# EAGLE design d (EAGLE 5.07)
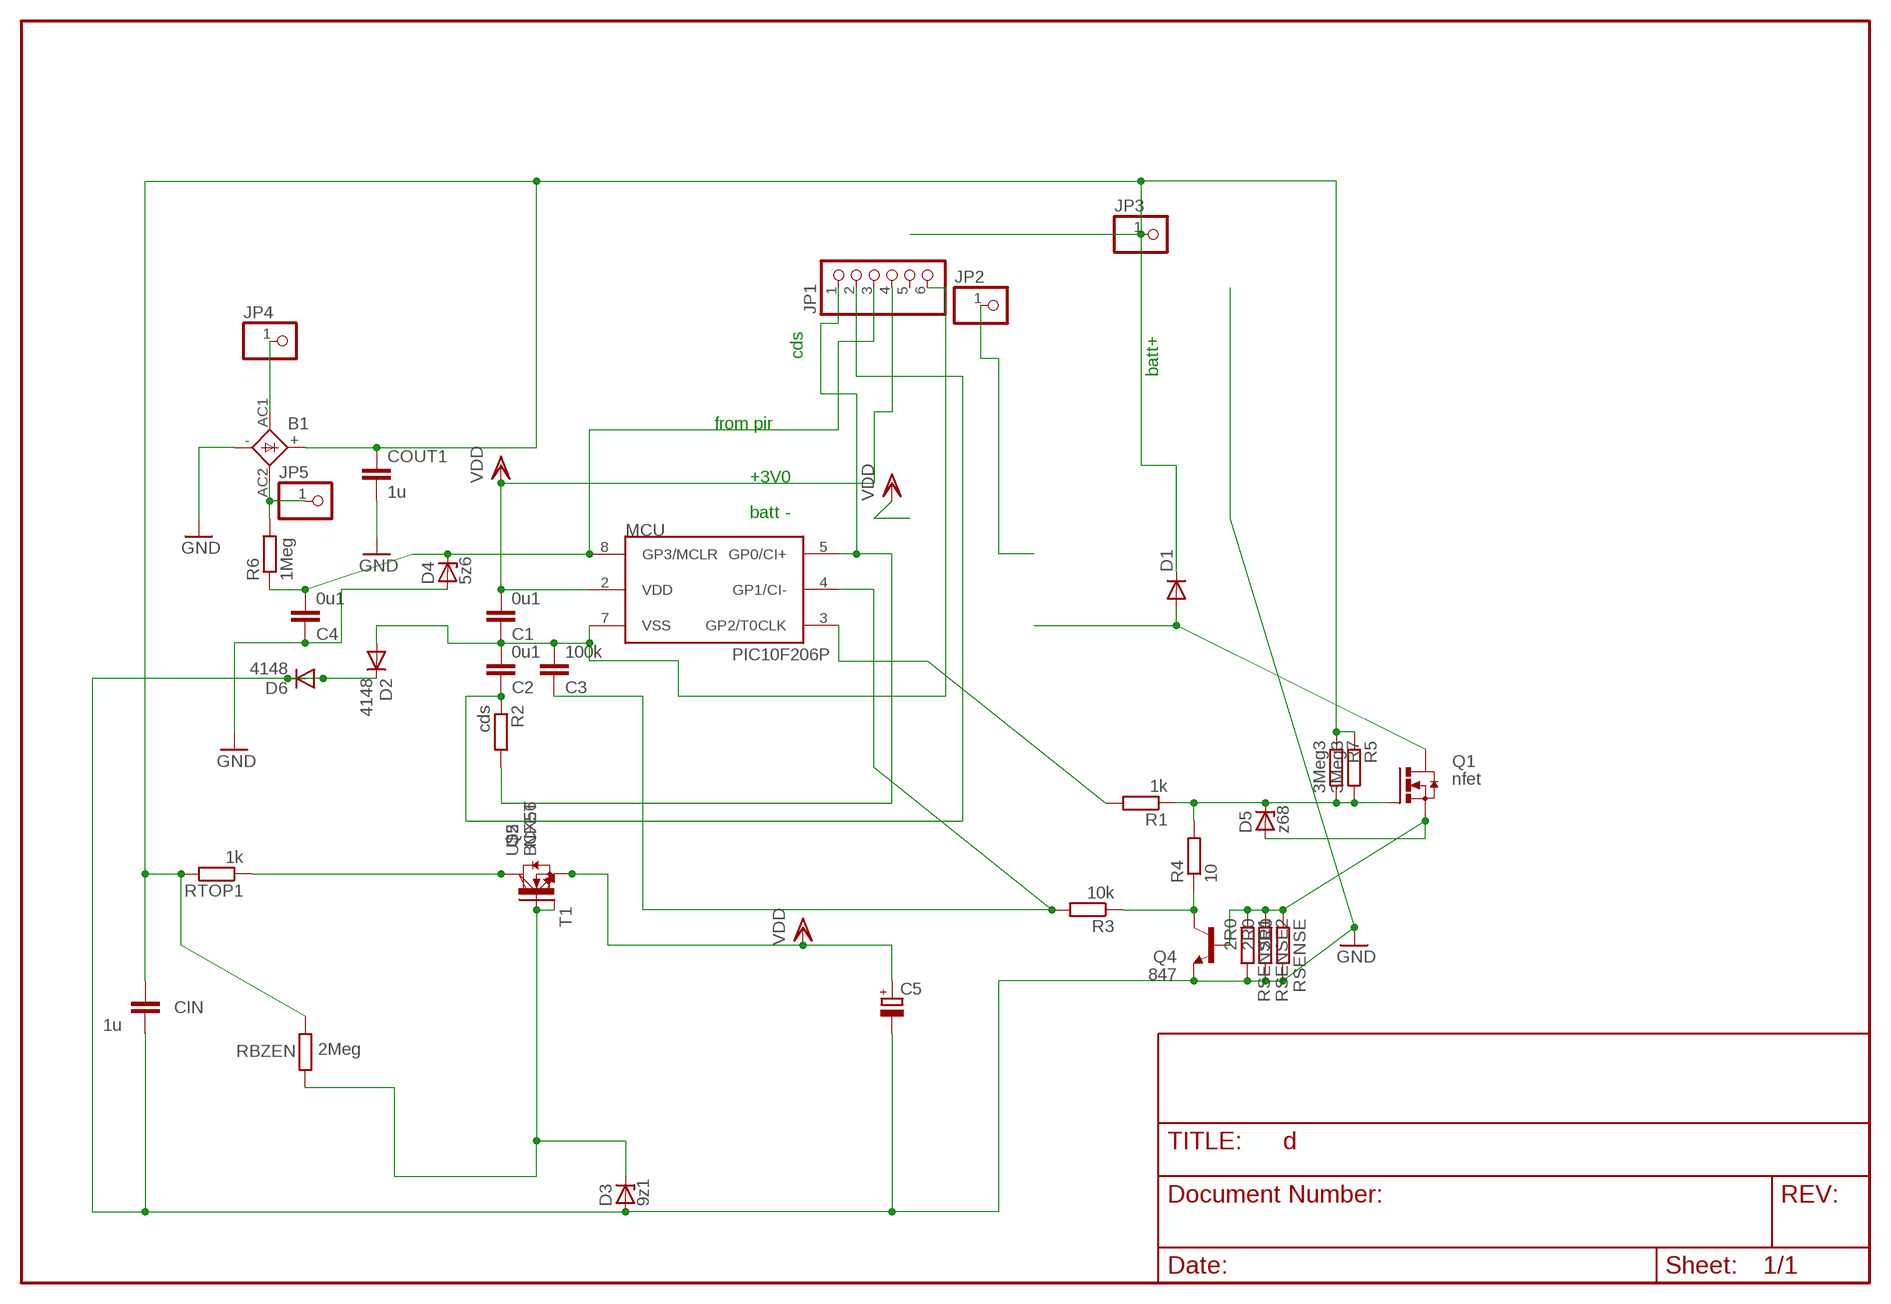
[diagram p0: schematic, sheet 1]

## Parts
B1  1KAB  [1KAB]
C1  0u1  C-EUC1206  [C1206]
C2  0u1  C-EUC0805  [C0805]
C3  100k  C-EUC1206  [C1206]
C4  0u1  C-EUC1206  [C1206]
C5  CPOL-EUSANYO_SMD_C6  [SANYO-OSCON_SMD_C6]
CIN  1u  C-EU050-024X044  [C050-024X044]
COUT1  1u  C-EU075-032X103  [C075-032X103]
D1  DIODE-SMC  [SMC]
D2  4148  1N4148MINIMELF  [MINIMELF]
D3  9z1  ZENER-DIODESOD80C  [SOD80C]
D4  5z6  ZENER-DIODESOD80C  [SOD80C]
D5  z68  ZENER-DIODESOD80C  [SOD80C]
D6  4148  1N4148MINIMELF  [MINIMELF]
JP1  PINHD-1X6  [1X06BOX]
JP2  PINHD-1X11X0.4  [1X01]
JP3  PINHD-1X11X0.4  [1X01]
JP4  PINHD-1X11X0.4  [1X01]
JP5  PINHD-1X11X0.4  [1X01]
MCU  PIC10F206P  [DIL8]
Q1  nfet  N-HEXFET_DPAK-  [TO252]
Q4  847  BC847ASMD  [SOT23]
Q5  NFET  N-HEXFET_DPAK-  [TO252]
R1  1k  R-EU_R0805  [R0805]
R2  cds  R-EU_0204/2V  [0204V]
R3  10k  R-EU_R1206  [R1206]
R4  10  R-EU_R1206  [R1206]
R5  3Meg3  R-EU_R2010  [R2010]
R6  1Meg  R-EU_  [0207/27]
R7  3Meg3  R-EU_0207/15  [0207/15]
RBZEN  2Meg  R-EU_0204/7  [0204/7]
RSENSE  2R0  R-EU_0207/15  [0207/15]
RSENSE1  2R0  R-EU_R1210  [R1210]
RSENSE2  2R0  R-EU_R2512  [R2512]
RTOP1  1k  R-EU_R1206  [R1206]
T1  -NPN-TO126V  [TO126V]
U$2  BCX56  [SOT223]

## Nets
AC1: B1.AC1 JP4.1
AC2: B1.AC2 JP5.1 R6.2
C: Q5.3(D) RTOP1.1 T1.2(C) U$2.2(C)
CB: D3.C Q5.1(G) RBZEN.2 T1.3(B) U$2.1(B)
GND: B1.- C4.1 C5.- CIN.2 COUT1.2 D2.C D3.A D4.A D6.A D6.C Q4.2(E) RSENSE1.2 RSENSE2.2 RSENSE.2
HOT: D1.A Q1.3(D)
LED-: JP2.1
N$1: Q4.3(C) R3.1 R4.1
N$2: JP1.1 MCU.5(GP0/CI+) R2.2
N$4: C3.1 MCU.4(GP1/CI-) R3.2
N$6: C4.2 D4.C JP1.3 MCU.8(GP3/MCLR) R6.1
N$7: D5.C Q1.1(G) R1.1 R4.2 R5.2 R7.2
N$11: C2.1 JP1.2 R2.1
N$14: MCU.3(GP2/T0CLK) R1.2
N$17: D5.A Q1.2(S) Q4.1(B) RSENSE1.1 RSENSE2.1 RSENSE.1
VDD: C1.2 C5.+ JP1.4 MCU.2(VDD) Q5.2(S) T1.1(E) U$2.3(E)
VPLUS: B1.+ CIN.1 COUT1.1 D1.C JP3.1 R5.1 R7.1 RBZEN.1 RTOP1.2
VSS: C1.1 C2.2 C3.2 D2.A JP1.6 MCU.7(VSS)
Unconnected: JP1.5

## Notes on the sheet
- cds
- batt+
- from pir
- +3V0
- batt -

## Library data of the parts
B1 = rectifier:1KAB: RECTIFIER grid 5,08 x 5,08 mm
C1-C4 CIN COUT1 = rcl:C-EU: CAPACITOR, European symbol
C5 = rcl-2:CPOL-EU: POLARIZED CAPACITOR, European symbol
D1 = diode-1:DIODE-: DIODE
D2 D6 = diode-1:1N4148: DIODE
D3-D5 = diode:ZENER-DIODE: Z-Diode
JP1 = pinhead:PINHD-1X6: PIN HEADER
JP2-JP5 = pinhead:PINHD-1X1: PIN HEADER
MCU = microchip-3:PIC10F2*: uPC nW 0,25/0,5k Program Flash memory Comparator
Q1 Q5 = transistor-power:N-HEXFET_?-*: HEXFET® Power MOSFET
Q4 = transistor-npn:BC847*: NPN Transistor
R1-R5 R7 RBZEN RSENSE RSENSE1 RSENSE2 RTOP1 = rcl:R-EU_: RESISTOR, European symbol
R6 = rcl-2:R-EU_: RESISTOR, European symbol
T1 = transistor:*-NPN-: NPN Transistror BF959 corrected 2008.03.06
U$2 = transistor-power:BCX56

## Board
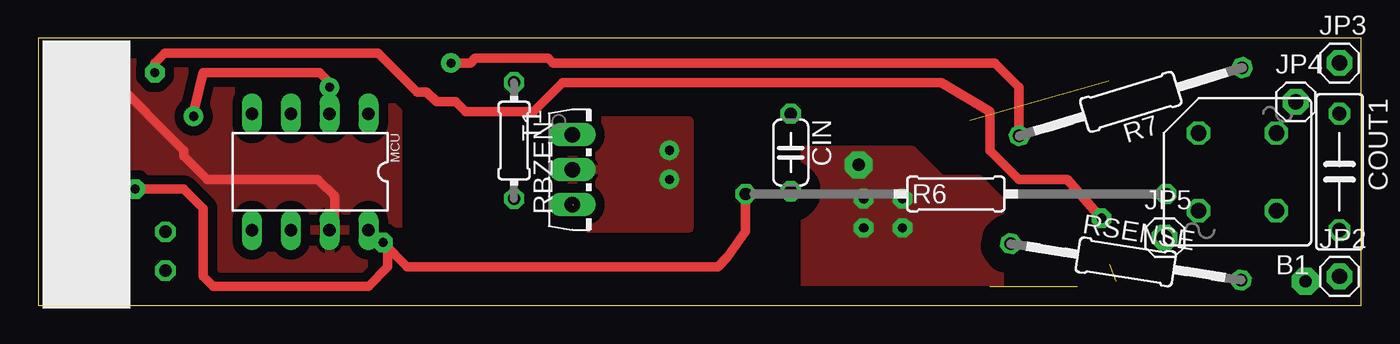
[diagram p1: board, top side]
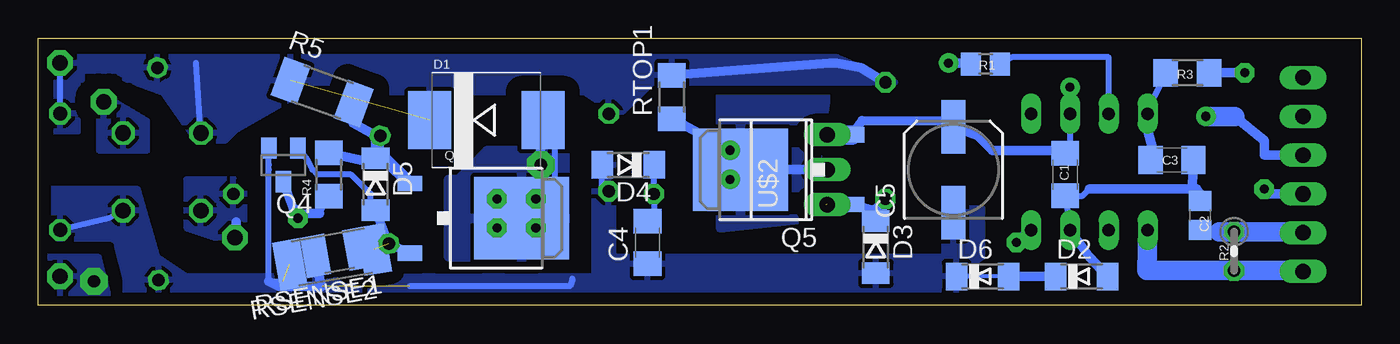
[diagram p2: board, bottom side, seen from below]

Size 86.52 x 17.5 mm. Coordinates in mm from the lower left corner, seen from the top.
Outline: 0,0 86.52,0 86.52,17.5 0,17.5 0,0
Copper layers (1*16): Top 0.035mm / dielectric 1.5mm / Bottom 0.035mm
Design rules "default *": minimum track width 10mil, minimum drill 24mil, track to track 8mil, track to pad 8mil, pad to pad 8mil, via to via 8mil, smd to smd 8mil, copper to edge 20mil, drill to drill 8mil, minimum pad ring 10mil, minimum via ring 8mil, stop-mask expansion 4mil, vias tented up to drill 0mil, thermal gap 10mil

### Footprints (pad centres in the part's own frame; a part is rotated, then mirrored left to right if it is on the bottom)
1KAB = drill 1.016 octagon: + 2.54,-2.54; - -2.54,2.54; AC1 -2.54,-2.54; AC2 2.54,2.54
C1206 = smd 1.6 x 1.8: 1 -1.4,0; 2 1.4,0
C0805 = smd 1.3 x 1.5: 1 -0.95,0; 2 0.95,0
SANYO-OSCON_SMD_C6 = smd 3.5 x 1.6: + 2.8,0; - -2.8,0
C050-024X044 = drill 0.813 octagon: 1 -2.54,0; 2 2.54,0
C075-032X103 = drill 0.914 octagon: 1 -3.81,0; 2 3.81,0
SMC = smd 2.8 x 3.8: A 3.7,0; C -3.7,0
MINIMELF = smd 1.4 x 1.8: A 1.7,0; C -1.7,0
SOD80C = smd 1.4 x 1.8: A 1.7,0; C -1.7,0
1X06BOX = drill 1.016 long: 1 -6.35,0; 2 -3.81,0; 3 -1.27,0; 4 1.27,0; 5 3.81,0; 6 6.35,0
1X01 = drill 1 pad 1.676 octagon: 1 0,0
DIL8 = drill 0.813 long: 1 -3.81,-3.81; 2 -1.27,-3.81; 3 1.27,-3.81; 4 3.81,-3.81; 5 3.81,3.81; 6 1.27,3.81; 7 -1.27,3.81; 8 -3.81,3.81
TO252 = smd 1 x 1.6: 1 -2.28,-3.53; 2 2.28,-3.53 | smd 5.4 x 6.2: 3 0,3.77
SOT23 = smd 1 x 1.4: 1 -0.95,-1.1; 2 0.95,-1.1; 3 0,1.1
R0805 = smd 1.3 x 1.5: 1 -0.95,0; 2 0.95,0
0204V = drill 0.813 octagon: 1 -1.27,0; 2 1.27,0
R1206 = smd 1.6 x 1.803: 1 -1.422,0; 2 1.422,0
R2010 = smd 1.8 x 2.7: 1 -2.2,0; 2 2.2,0
0207/27 = drill 0.813 octagon: 1 -13.75,0; 2 13.75,0
0207/15 = drill 0.813 octagon: 1 -7.62,0; 2 7.62,0
0204/7 = drill 0.813 octagon: 1 -3.81,0; 2 3.81,0
R1210 = smd 1.6 x 2.7: 1 -1.4,0; 2 1.4,0
R2512 = smd 1.8 x 3.2: 1 -2.8,0; 2 2.8,0
TO126V = drill 1.016 long: 1 -2.286,-1.27; 2 0,-1.27; 3 2.286,-1.27
SOT223 = smd 1.219 x 2.235: 1 -2.311,-3.099; 2 0,-3.099; 3 2.311,-3.099 | smd 3.6 x 2.2: 4 0,3.099

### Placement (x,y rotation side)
B1  78.42,8.75 180 top
C1  19.37,8.57 90 bottom
C2  10.54,5.91 90 bottom
C3  12.38,9.53 0 bottom
C4  46.67,4.13 90 bottom
C5  26.67,8.89 90 bottom
CIN  49.21,10.02 270 top
COUT1  85.09,8.75 270 top
D1  57.21,12.13 0 bottom
D2  18.3,1.91 0 bottom
D3  31.75,3.81 270 bottom
D4  47.94,9.21 180 bottom
D5  64.45,7.94 270 bottom
D6  24.77,1.91 0 bottom
JP1  3.81,8.57 90 top
JP2  85.09,1.91 0 top
JP3  85.09,15.88 0 top
JP4  82.23,13.34 0 top
JP5  73.66,4.45 0 top
MCU  17.78,8.75 180 top
Q1  58.67,5.71 270 bottom
Q4  70.48,9.21 180 bottom
Q5  36.83,8.89 90 bottom
R1  24.57,15.81 0 bottom
R2  8.32,3.56 270 bottom
R3  11.37,15.24 180 bottom
R4  67.51,8.57 90 bottom
R5  67.94,13.97 340 bottom
R6  60.01,7.3 0 top
R7  71.44,13.34 197 top
RBZEN  31.11,10.79 270 top
RSENSE  71.12,2.86 351 top
RSENSE1  66.99,3.49 190 bottom
RSENSE2  67.31,3.17 190 bottom
RTOP1  45.09,13.65 90 bottom
T1  36.2,8.89 270 top
U$2  38.1,8.89 90 bottom

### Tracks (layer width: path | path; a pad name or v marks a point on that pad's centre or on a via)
AC1
  pour Bottom (isolate 0.61): 79.38,12.06 82.55,13.97 82.55,10.16 79.38,10.16
AC2
  Bottom 0.406: B1.AC2 75.42,6.35
  Bottom 0.61: JP5.1 73.58,5.48
  pour Bottom (isolate 0.813, rank 2): 73.03,3.81 73.03,8.26 76.83,8.26 76.83,5.08
C  (via drill 0.6 pad 1.27)
  Bottom 0.406: T1.2 U$2.2 | v41.27,10.16 40.64,10.16 40.64,9.53
  Bottom 0.61: 40.01,8.89 40.64,9.53 | U$2.2 39.37,8.89 | 39.37,8.89 40.01,8.89 | RTOP1.1 43.33,11.28 42.55,9.53 39.37,8.89 | 40.01,8.89 Q5.3
  other vias: 41.27,8.26
  pour Bottom (isolate 0.61, rank 5): 34.92,13.97 41.91,13.97 41.91,5.08 36.2,5.71
  pour Top (isolate 0.61, rank 4): 34.92,12.06 42.55,12.06 42.55,5.08 34.92,5.08
CB  (1 unrouted)
  Bottom 0.61: D3.C 31.75,6.35 RBZEN.2 31.39,6.07 Q5.1 34.29,6.61
  Bottom 1.27: 34.29,6.61 T1.3
GND  (2 unrouted)
  Bottom 0.254: D6.A D6.C
  Bottom 0.406: COUT1.2 81.92,5.71 B1.- | 62.23,1.27 51.75,1.27 51.58,1.76 | Q4.2 71.44,9.21 71.44,8.89 71.44,1.59 70.48,1.59 70.17,1.27 | CIN.2 49.64,7.48 D4.A
  Bottom 0.61: D2.C D6.A | RSENSE1.2 68.05,1.38 67.94,1.27 70.8,1.27 71.44,1.59
  pour Bottom (isolate 0.813, rank 4): 80.01,7.62 85.72,7.62 85.72,3.81 83.19,3.81 81.28,0.64 25.72,0.64 25.72,2.54 24.77,3.17 24.77,6.35 27.3,6.35 27.3,3.17 48.9,3.17 48.9,9.53 50.16,9.53 50.16,1.91 76.83,1.91 78.74,3.17
HOT  (via drill 0.6 pad 1.27, 0.8 pad 1.78)
  Bottom 0.406: D1.A 52.7,12.13 52.7,11.43 52.7,6.35 54.91,6.35 Q1.3
  Bottom 0.61: v53.66,9.21 53.66,11.11 53.34,11.43 52.7,11.43
  other vias: 53.98,6.99 53.98,5.08 56.52,5.08 56.52,6.99
  pour Bottom: 52.07,10.16 57.15,10.16 59.05,8.26 59.69,8.26 59.69,3.17 52.07,3.17
  pour Top (isolate 1.27): 50.16,10.16 57.15,10.16 59.05,8.26 62.87,8.26 62.87,1.27 50.16,1.27
LED-  (via drill 0.8 pad 1.78)
  other vias: 82.87,1.59
  pour Bottom (isolate 0.61, rank 3): 82.55,3.17 86.36,3.17 86.36,0.64 81.92,0.64
N$1  (via drill 0.6 pad 1.27)
  Top 0.61: v7.62,15.24 7.62,15.88 8.26,16.51 22.23,16.51 24.77,13.97 25.4,13.97 26.04,13.34 27.3,13.34 27.94,12.7 32.38,12.7 34.29,14.61 59.05,14.61 62.23,12.7 62.23,10.16 64.14,8.26 67.31,8.26 v69.53,5.71
  Bottom 0.406: 68.9,6.03 69.66,6.29 69.85,6.35 | 68.11,6.03 R4.1
  Bottom 0.61: 69.85,6.35 Q4.3 | 68.9,6.03 68.11,6.03 | R3.1 v7.62,15.24 | v69.53,5.71 69.85,6.1 69.66,6.29
N$2
  Bottom 0.406: JP1.1 4.06,2.29
  Bottom 1.27: 4.06,2.29 R2.2 14.03,2.29 MCU.5
N$4
  Bottom 0.406: R3.2 13.97,12.79 MCU.4 13.97,11.43 | C3.1 13.65,10.35
  Bottom 0.61: 13.65,10.35 13.97,11.43
N$6  (via drill 0.6 pad 1.27)
  Top 0.61: R6.1 46.26,4.86 45.09,3.17 44.45,2.54 24.13,2.54 v22.54,4.13 22.86,3.81 22.86,2.54 21.59,1.27 11.43,1.27 10.79,1.91 10.79,6.35 9.53,7.62 v6.35,7.62
  Bottom 0.406: C4.2 46.26,5.53 R6.1 46.26,9.21 D4.C
  Bottom 0.61: MCU.8 21.73,4.94 v22.54,4.13 | JP1.3 6.03,7.3 v6.35,7.62
N$7  (via drill 0.6 pad 1.27)
  Top 0.61: v26.99,15.88 28.26,15.88 28.57,16.19 33.34,16.19 33.66,15.88 53.66,15.88 62.55,15.88 64.14,14.29 64.14,11.54 R7.2
  Bottom 0.406: 65.92,11.95 R5.2 | D5.C 64.45,10.27 | D5.C 64.73,9.36 | R7.2 64.12,9.97 D5.C
  Bottom 0.61: v26.99,15.88 26.22,15.88 R1.1 | 65.92,11.95 64.45,11.11 64.45,10.27 | 64.73,9.36 R4.2
  Bottom 0.813: Q1.1 63.82,9.58 D5.C
N$11
  Bottom 0.406: 9.27,4.83 C2.1 | JP1.2 4.06,4.83
  Bottom 1.27: 9.27,4.83 R2.1 4.06,4.83
N$14
  Bottom 0.406: MCU.3 16.51,16.25 22.86,16.25 23.56,15.81 R1.2
N$17  (1 unrouted)
  Bottom 0.406: Q4.1 68.9,9.53 68.58,8.89 68.26,8.57 66.04,8.57 64.77,7.3 64.77,6.55 D5.A
  Bottom 0.61: RSENSE.1 D5.A | RSENSE.1 RSENSE1.1 | Q1.2 RSENSE.1
VDD  (via drill 0.6 pad 1.27)
  Top 0.61: v10.16,12.38 10.16,12.7 10.79,15.24 18.41,15.24 19.05,14.61 v19.05,14.29 | MCU.2 19.05,12.7
  Bottom 0.406: 19.05,12.7 MCU.2 19.05,10.29 C1.2 | T1.1 34.34,11.18 U$2.3
  Bottom 0.61: JP1.4 6.35,9.84 6.35,10.79 8.26,12.38 | v19.05,14.29 MCU.2 | Q5.2 32.65,12.12 27.3,12.06 26.67,12.06 C5.+ 25.06,11.09 24.13,10.16 19.55,10.16 C1.2
  Bottom 1.27: 8.26,12.38 v10.16,12.38 | Q5.2 34.28,11.17 T1.1
VPLUS  (1 unrouted)
  Bottom 0.406: B1.+ 76.2,15.88 | COUT1.1 JP3.1
  Bottom 0.61: RBZEN.1 32.7,15.56 34.29,15.88 34.77,15.88 RTOP1.2
  pour Bottom (isolate 1.016, rank 3): 86.36,11.43 83.82,11.43 83.82,14.61 81.92,15.24 78.42,13.97 76.2,10.79 74.3,10.79 73.66,11.43 69.22,13.97 68.58,14.61 64.77,14.61 64.14,13.97 50.8,13.97 48.9,12.7 48.26,12.7 46.35,14.61 30.48,14.61 34.92,16.51 86.36,17.14
VSS
  Top 0.61: JP1.6 4.76,14.92 9.53,10.16 9.53,9.78 11.04,8.27 18.27,8.27 C1.1 19.37,5.26 MCU.7
  Bottom 0.406: MCU.7 19.05,5.58 C1.1 18.23,7.17 17.78,7.62 | 10.77,7.62 11.05,7.81
  Bottom 0.61: D2.A 17.78,3.17 MCU.7 | 17.78,7.62 10.77,7.62 10.54,7.33 C2.2 | 11.05,7.81 C3.2
  pour Top (isolate 0.61): 3.17,15.88 20.32,15.88 23.5,12.7 23.5,2.54 22.86,1.91 3.17,1.91 3.17,2.54 3.17,12.06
